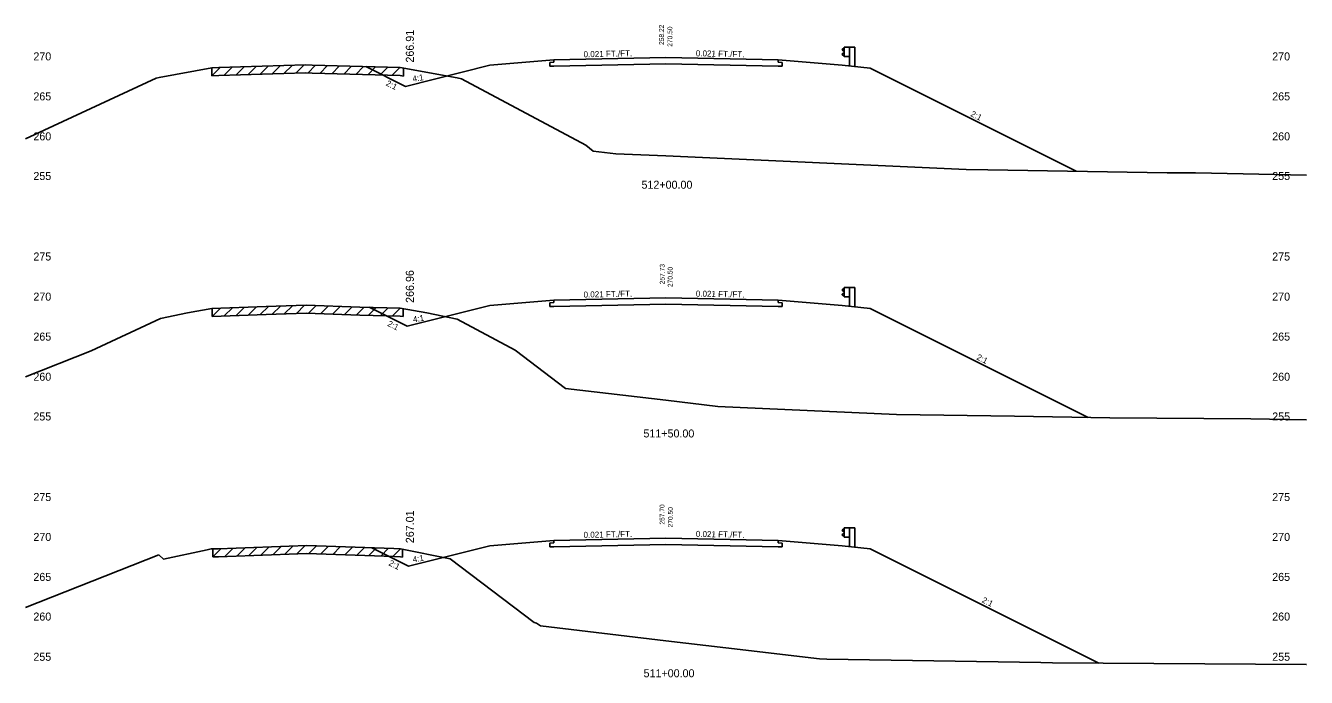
# Model space of a CAD drawing. Extents: x 883 to 1160, y 1002 to 4323.
# Drawn here: x 1000 to 1160, y 2393.1 to 2474.5 of the extents above; entities that cross this region are included whole.
import ezdxf

# ---------------------------------------------------------------- set-up
doc = ezdxf.new("R2010")
doc.units = 0
for name, color, linetype in [('Level 1', 7, 'Continuous'), ('Level 10', 7, 'Continuous'), ('Level 11', 7, 'Continuous'), ('Level 12', 7, 'Continuous'), ('Level 24', 7, 'Continuous'), ('Level 3', 7, 'Continuous'), ('Level 32', 7, 'Continuous'), ('Level 33', 7, 'Continuous'), ('Level 59', 7, 'Continuous'), ('Level 6', 7, 'Continuous'), ('Level 60', 7, 'Continuous'), ('Level 61', 7, 'Continuous'), ('Level 7', 7, 'Continuous')]:
    doc.layers.add(name, color=color, linetype=linetype)

msp = doc.modelspace()

# ---------------------------------------------------------------- linework, layer by layer
at = {"layer": 'Level 11'}
for p, q in [((1066, 2469.91), (1065.5, 2469.9)), ((1065.5, 2469.9), (1065.5, 2469.42)), ((1065.5, 2469.42), (1066, 2469.43)), ((1066, 2470.21), (1066, 2469.91)), ((1094, 2469.91), (1094, 2470.21)), ((1094.5, 2469.9), (1094, 2469.91)), ((1094, 2469.43), (1094.5, 2469.42)), ((1094.5, 2469.42), (1094.5, 2469.9)), ((1066, 2440.21), (1066, 2439.91)), ((1094, 2439.91), (1094, 2440.21)), ((1066, 2439.91), (1065.5, 2439.9)), ((1065.5, 2439.9), (1065.5, 2439.42)), ((1065.5, 2439.42), (1066, 2439.43)), ((1094.5, 2439.9), (1094, 2439.91)), ((1094, 2439.43), (1094.5, 2439.42)), ((1094.5, 2439.42), (1094.5, 2439.9)), ((1066, 2409.91), (1065.5, 2409.9)), ((1065.5, 2409.9), (1065.5, 2409.42)), ((1066, 2410.21), (1066, 2409.91)), ((1094, 2409.91), (1094, 2410.21)), ((1094.5, 2409.9), (1094, 2409.91)), ((1094.5, 2409.42), (1094.5, 2409.9)), ((1065.5, 2409.42), (1066, 2409.43)), ((1094, 2409.43), (1094.5, 2409.42))]:
    msp.add_line(p, q, dxfattribs=at)
at = {"layer": 'Level 12'}
for p, q in [((1080, 2469.72), (1066, 2469.43)), ((1094, 2469.43), (1080, 2469.72)), ((1080, 2439.72), (1066, 2439.43)), ((1094, 2439.43), (1080, 2439.72)), ((1080, 2409.72), (1066, 2409.43)), ((1094, 2409.43), (1080, 2409.72))]:
    msp.add_line(p, q, dxfattribs=at)
at = {"layer": 'Level 24'}
for p, q in [((1102.27, 2471.72), (1102, 2471.52)), ((1102, 2471.52), (1102, 2471.47)), ((1102, 2471.47), (1102.27, 2471.27)), ((1102, 2470.95), (1102.27, 2471.15)), ((1102, 2470.9), (1102, 2470.95)), ((1102.27, 2470.7), (1102, 2470.9)), ((1102.27, 2470.63), (1102.27, 2471.79)), ((1102.27, 2471.79), (1102.94, 2471.79)), ((1102.27, 2470.63), (1102.94, 2470.63)), ((1102.94, 2471.79), (1102.94, 2469.45)), ((1102.94, 2471.79), (1103.6, 2471.79)), ((1103.6, 2471.79), (1103.6, 2469.38)), ((1102.27, 2441.72), (1102, 2441.52)), ((1102.27, 2440.63), (1102.27, 2441.79)), ((1102.27, 2441.79), (1102.94, 2441.79)), ((1102.94, 2441.79), (1102.94, 2439.45)), ((1102.94, 2441.79), (1103.6, 2441.79)), ((1103.6, 2441.79), (1103.6, 2439.38)), ((1102, 2441.52), (1102, 2441.47)), ((1102, 2441.47), (1102.27, 2441.27)), ((1102, 2440.95), (1102.27, 2441.15)), ((1102, 2440.9), (1102, 2440.95)), ((1102.27, 2440.7), (1102, 2440.9)), ((1102.27, 2440.63), (1102.94, 2440.63)), ((1102.27, 2411.72), (1102, 2411.52)), ((1102, 2411.52), (1102, 2411.47)), ((1102, 2411.47), (1102.27, 2411.27)), ((1102.27, 2410.63), (1102.27, 2411.79)), ((1102.27, 2411.79), (1102.94, 2411.79)), ((1102.94, 2411.79), (1102.94, 2409.45)), ((1102.94, 2411.79), (1103.6, 2411.79)), ((1103.6, 2411.79), (1103.6, 2409.38)), ((1102, 2410.95), (1102.27, 2411.15)), ((1102, 2410.9), (1102, 2410.95)), ((1102.27, 2410.7), (1102, 2410.9)), ((1102.27, 2410.63), (1102.94, 2410.63))]:
    msp.add_line(p, q, dxfattribs=at)
at = {"layer": 'Level 59'}
for p, q in [((1066, 2470.21), (1080, 2470.5)), ((1080, 2470.5), (1094, 2470.21)), ((1066, 2440.21), (1080, 2440.5)), ((1080, 2440.5), (1094, 2440.21)), ((1066, 2410.21), (1080, 2410.5)), ((1080, 2410.5), (1094, 2410.21))]:
    msp.add_line(p, q, dxfattribs=at)
at = {"layer": 'Level 6'}
for p, q in [((1058, 2469.54), (1066, 2470.21)), ((1094, 2470.21), (1102, 2469.54)), ((1102, 2469.54), (1105.5, 2469.19)), ((1058, 2439.54), (1066, 2440.21)), ((1094, 2440.21), (1102, 2439.54)), ((1102, 2439.54), (1105.5, 2439.19)), ((1058, 2409.54), (1066, 2410.21)), ((1094, 2410.21), (1102, 2409.54)), ((1102, 2409.54), (1105.5, 2409.19))]:
    msp.add_line(p, q, dxfattribs=at)
at = {"layer": 'Level 60'}
for p, q in [((1016.69, 2468.03), (1023.28, 2469.23)), ((1023.28, 2469.23), (1024.12, 2469.26)), ((1024.12, 2469.26), (1034.96, 2469.58)), ((1034.96, 2469.58), (1035.8, 2469.55)), ((1035.8, 2469.55), (1046.79, 2469.25)), ((1046.79, 2469.25), (1053.93, 2467.97)), ((1000, 2460.37), (1016.29, 2467.95)), ((1016.29, 2467.95), (1016.69, 2468.03)), ((1053.93, 2467.97), (1054.45, 2467.87)), ((1054.45, 2467.87), (1069.97, 2459.55)), ((1069.97, 2459.55), (1070.9, 2458.84)), ((1070.9, 2458.84), (1073.74, 2458.5)), ((1073.74, 2458.5), (1080, 2458.22)), ((1080, 2458.22), (1117.49, 2456.54)), ((1117.49, 2456.54), (1120.19, 2456.5)), ((1120.19, 2456.5), (1142.61, 2456.12)), ((1142.61, 2456.12), (1146.15, 2456.1)), ((1146.15, 2456.1), (1160, 2455.81)), ((1016.87, 2437.93), (1020.21, 2438.64)), ((1020.21, 2438.64), (1023.25, 2439.19)), ((1023.25, 2439.19), (1030.07, 2439.44)), ((1030.07, 2439.44), (1035.06, 2439.59)), ((1035.06, 2439.59), (1041.74, 2439.36)), ((1041.74, 2439.36), (1046.81, 2439.22)), ((1046.81, 2439.22), (1050.11, 2438.63)), ((1050.11, 2438.63), (1053.9, 2437.86)), ((1008.2, 2433.9), (1016.87, 2437.93)), ((1053.9, 2437.86), (1061.17, 2433.97)), ((1000, 2430.65), (1008.2, 2433.9)), ((1061.17, 2433.97), (1067.44, 2429.21)), ((1067.44, 2429.21), (1080, 2427.73)), ((1080, 2427.73), (1086.46, 2426.96)), ((1086.46, 2426.96), (1108.79, 2425.96)), ((1108.79, 2425.96), (1123.52, 2425.73)), ((1123.52, 2425.73), (1135.45, 2425.53)), ((1135.45, 2425.53), (1153.07, 2425.42)), ((1153.07, 2425.42), (1160, 2425.28)), ((1000, 2401.84), (1016.65, 2408.41)), ((1016.65, 2408.41), (1017.24, 2407.89)), ((1017.24, 2407.89), (1022.67, 2409.04)), ((1022.67, 2409.04), (1023.2, 2409.16)), ((1023.2, 2409.16), (1024.08, 2409.19)), ((1024.08, 2409.19), (1035.14, 2409.59)), ((1035.14, 2409.59), (1046, 2409.22)), ((1046, 2409.22), (1046.83, 2409.18)), ((1046.83, 2409.18), (1053.02, 2407.93)), ((1053.02, 2407.93), (1063.52, 2399.96)), ((1063.52, 2399.96), (1063.83, 2399.9)), ((1063.83, 2399.9), (1064.33, 2399.56)), ((1064.33, 2399.56), (1080, 2397.7)), ((1080, 2397.7), (1087.49, 2396.81)), ((1087.49, 2396.81), (1099.17, 2395.43)), ((1099.17, 2395.43), (1100.09, 2395.38)), ((1100.09, 2395.38), (1126.84, 2394.97)), ((1126.84, 2394.97), (1128.29, 2394.94)), ((1128.29, 2394.94), (1159.99, 2394.74)), ((1159.99, 2394.74), (1160, 2394.74))]:
    msp.add_line(p, q, dxfattribs=at)
at = {"layer": 'Level 61'}
for p, q in [((1024.3, 2469.26), (1023.26, 2468.22)), ((1023.26, 2469.22), (1023.26, 2468.22)), ((1025.79, 2469.31), (1024.76, 2468.27)), ((1027.29, 2469.35), (1026.26, 2468.32)), ((1028.79, 2469.4), (1027.76, 2468.36)), ((1030.29, 2469.44), (1029.26, 2468.41)), ((1031.79, 2469.49), (1030.76, 2468.45)), ((1033.29, 2469.53), (1032.26, 2468.5)), ((1034.79, 2469.58), (1033.76, 2468.54)), ((1036.23, 2469.54), (1035.26, 2468.57)), ((1037.73, 2469.5), (1036.76, 2468.53)), ((1039.23, 2469.46), (1038.26, 2468.49)), ((1040.73, 2469.42), (1039.76, 2468.45)), ((1042.23, 2469.38), (1041.26, 2468.4)), ((1043.73, 2469.34), (1042.76, 2468.36)), ((1045.23, 2469.3), (1044.26, 2468.32)), ((1046.73, 2469.26), (1045.76, 2468.28)), ((1047.22, 2468.18), (1047.22, 2469.18)), ((1023.26, 2468.22), (1023.28, 2468.23)), ((1023.28, 2468.23), (1024.12, 2468.26)), ((1024.12, 2468.26), (1034.96, 2468.58)), ((1034.96, 2468.58), (1035.8, 2468.55)), ((1035.8, 2468.55), (1046.79, 2468.25)), ((1046.79, 2468.25), (1047.22, 2468.18)), ((1024.36, 2439.23), (1023.32, 2438.19)), ((1023.32, 2439.19), (1023.32, 2438.19)), ((1023.32, 2438.19), (1030.07, 2438.44)), ((1025.86, 2439.28), (1024.82, 2438.25)), ((1027.36, 2439.34), (1026.32, 2438.3)), ((1028.86, 2439.39), (1027.82, 2438.35)), ((1030.36, 2439.44), (1029.32, 2438.41)), ((1030.07, 2438.44), (1035.06, 2438.59)), ((1031.85, 2439.49), (1030.82, 2438.46)), ((1033.35, 2439.53), (1032.32, 2438.5)), ((1034.85, 2439.58), (1033.82, 2438.55)), ((1035.06, 2438.59), (1041.74, 2438.36)), ((1036.29, 2439.54), (1035.32, 2438.58)), ((1037.79, 2439.49), (1036.82, 2438.53)), ((1039.29, 2439.44), (1038.32, 2438.47)), ((1040.79, 2439.39), (1039.82, 2438.42)), ((1042.29, 2439.34), (1041.32, 2438.37)), ((1043.79, 2439.3), (1042.82, 2438.33)), ((1045.29, 2439.26), (1044.32, 2438.29)), ((1046.79, 2439.22), (1045.82, 2438.25)), ((1047.15, 2438.16), (1047.15, 2439.16)), ((1041.74, 2438.36), (1046.81, 2438.22)), ((1046.81, 2438.22), (1047.15, 2438.16)), ((1024.42, 2409.21), (1023.38, 2408.17)), ((1023.38, 2409.17), (1023.38, 2408.17)), ((1023.38, 2408.17), (1024.08, 2408.19)), ((1024.08, 2408.19), (1035.14, 2408.59)), ((1025.92, 2409.26), (1024.88, 2408.22)), ((1027.42, 2409.31), (1026.38, 2408.28)), ((1028.92, 2409.37), (1027.88, 2408.33)), ((1030.42, 2409.42), (1029.38, 2408.38)), ((1031.92, 2409.48), (1030.88, 2408.44)), ((1033.42, 2409.53), (1032.38, 2408.49)), ((1034.92, 2409.58), (1033.88, 2408.55)), ((1035.14, 2408.59), (1046, 2408.22)), ((1036.35, 2409.55), (1035.38, 2408.58)), ((1037.85, 2409.5), (1036.88, 2408.53)), ((1039.35, 2409.45), (1038.38, 2408.48)), ((1040.85, 2409.4), (1039.88, 2408.43)), ((1042.35, 2409.34), (1041.38, 2408.38)), ((1043.85, 2409.29), (1042.88, 2408.33)), ((1045.35, 2409.24), (1044.38, 2408.28)), ((1046.84, 2409.18), (1045.88, 2408.22)), ((1046, 2408.22), (1046.83, 2408.18)), ((1046.83, 2408.18), (1047.09, 2408.13)), ((1047.09, 2408.13), (1047.09, 2409.13))]:
    msp.add_line(p, q, dxfattribs=at)
at = {"layer": 'Level 7'}
for p, q in [((1042.52, 2469.37), (1047.45, 2466.91)), ((1058, 2469.54), (1047.45, 2466.91)), ((1105.5, 2469.19), (1131.26, 2456.31)), ((1042.91, 2439.33), (1047.65, 2436.96)), ((1058, 2439.54), (1047.65, 2436.96)), ((1105.5, 2439.19), (1132.73, 2425.58)), ((1043.24, 2409.31), (1047.85, 2407.01)), ((1058, 2409.54), (1047.85, 2407.01)), ((1105.5, 2409.19), (1134.08, 2394.9))]:
    msp.add_line(p, q, dxfattribs=at)

# ---------------------------------------------------------------- texts
at = {"layer": 'Level 1'}
for s, p in [('512+00.00', (1076.94, 2454.13)), ('511+50.00', (1077.18, 2423.08)), ('511+00.00', (1077.2, 2393.14))]:
    msp.add_text(s, height=1, dxfattribs=at).set_placement(p)
at = {"layer": 'Level 10'}
for s, p in [('258.22', (1079.74, 2472.08)), ('257.73', (1079.83, 2442.2)), ('257.70', (1079.81, 2412.2))]:
    msp.add_text(s, height=0.6, rotation=90, dxfattribs=at).set_placement(p)
at = {"layer": 'Level 3'}
for s, p in [(' 270', (1000.6, 2470.15)), (' 270', (1155.36, 2470.15)), (' 265', (1000.6, 2465.16)), (' 265', (1155.36, 2465.16)), (' 260', (1000.6, 2460.17)), (' 260', (1155.36, 2460.17)), (' 255', (1000.6, 2455.22)), (' 255', (1155.36, 2455.22)), (' 275', (1000.6, 2445.17)), (' 275', (1155.36, 2445.17)), (' 270', (1000.6, 2440.16)), (' 270', (1155.36, 2440.16)), (' 265', (1000.6, 2435.17)), (' 265', (1155.36, 2435.17)), (' 260', (1000.6, 2430.16)), (' 260', (1155.36, 2430.16)), (' 255', (1000.6, 2425.2)), (' 255', (1155.36, 2425.2)), (' 275', (1000.6, 2415.14)), (' 275', (1155.36, 2415.14)), (' 270', (1000.6, 2410.16)), (' 270', (1155.36, 2410.16)), (' 265', (1000.6, 2405.17)), (' 265', (1155.36, 2405.17)), (' 260', (1000.6, 2400.22)), (' 260', (1155.36, 2400.22)), (' 255', (1000.6, 2395.2)), (' 255', (1155.36, 2395.2))]:
    msp.add_text(s, height=1, dxfattribs=at).set_placement(p)
at = {"layer": 'Level 32'}
for s, rotation, p in [('0.021 FT./FT.', 1.1916, (1069.71, 2470.54)), ('0.021 FT./FT.', 358.8084, (1083.72, 2470.67)), ('2:1', 333.435, (1044.94, 2467.06)), ('4:1', 9.4623, (1048.39, 2467.47)), ('2:1', 333.435, (1117.98, 2463.23)), ('0.021 FT./FT.', 1.1916, (1069.71, 2440.54)), ('0.021 FT./FT.', 358.8084, (1083.72, 2440.67)), ('2:1', 333.435, (1045.13, 2437.04)), ('4:1', 9.4623, (1048.45, 2437.43)), ('2:1', 333.435, (1118.72, 2432.86)), ('0.021 FT./FT.', 1.1916, (1069.71, 2410.54)), ('0.021 FT./FT.', 358.8084, (1083.72, 2410.67)), ('4:1', 9.4623, (1048.42, 2407.47)), ('2:1', 333.435, (1045.28, 2407.16)), ('2:1', 333.435, (1119.39, 2402.53))]:
    msp.add_text(s, height=0.75, rotation=rotation, dxfattribs=at).set_placement(p)
at = {"layer": 'Level 33'}
for s, p in [('266.91', (1048.5, 2469.88)), ('266.96', (1048.5, 2439.88)), ('267.01', (1048.5, 2409.88))]:
    msp.add_text(s, height=1, rotation=90, dxfattribs=at).set_placement(p)
at = {"layer": 'Level 59'}
for p in [(1080.79, 2471.62), (1080.82, 2441.62), (1080.85, 2411.62)]:
    msp.add_text(' 270.50', height=0.6, rotation=90, dxfattribs=at).set_placement(p)

doc.saveas('drawing.dxf')
